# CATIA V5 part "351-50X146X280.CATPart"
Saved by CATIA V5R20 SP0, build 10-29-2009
Part number: 351-50X146X280
Definition: NONE
Nomenclature: 351-50X146X280
Source: Unknown
Description: 351-50X146X280
Bounding box of the stored display mesh (mm): x -10 to 270, y -32.5 to 32.5, z -32.5 to 32.5
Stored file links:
  C:\Users\Utente\Desktop\IO LAVORO\3D X SITO CF\X SITO\PLASTICA\351\351-50X146X280.CATPart
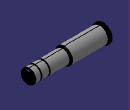
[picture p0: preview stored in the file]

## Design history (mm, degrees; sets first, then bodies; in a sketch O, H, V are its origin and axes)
Body1 "351-50X146X280" (main body)
  Solid1: solid without history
